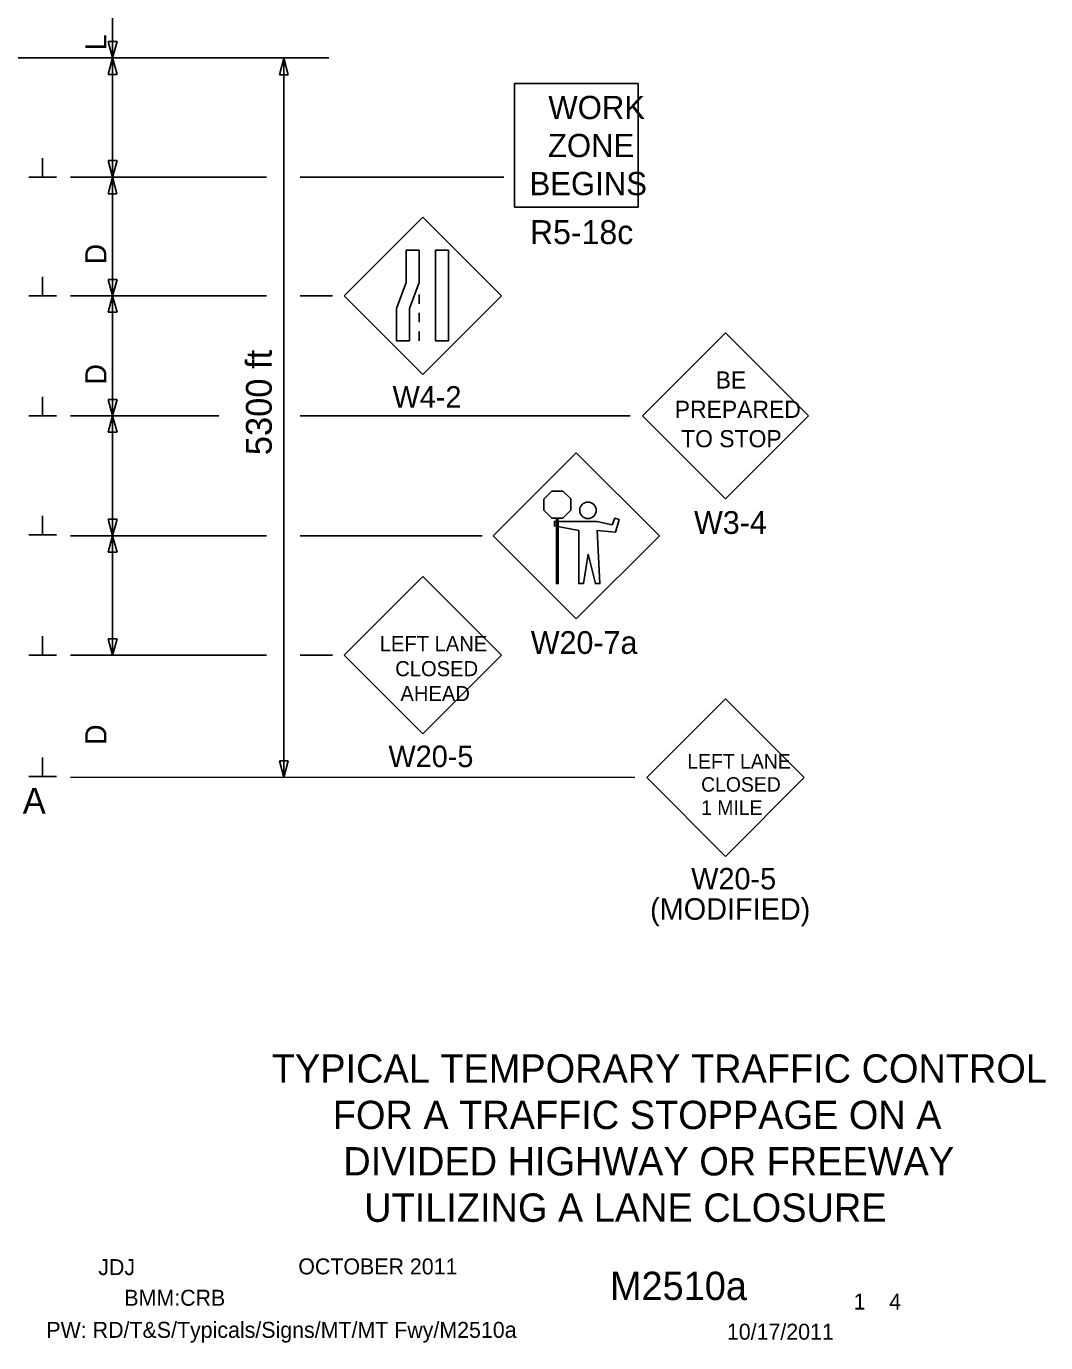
# Model space of a CAD drawing. Extents: x -1809 to 1557, y -1087 to 44.
# Drawn here: x -1388 to -993, y -949 to -438 of the extents above; entities that cross this region are included whole.
import ezdxf

# ---------------------------------------------------------------- set-up
doc = ezdxf.new("R2010")
doc.units = 0
for name, color, linetype in [('BORDER_SIGNAL_WO', 7, 'Continuous'), ('MT_STAGE_1A_NOTES', 7, 'Continuous'), ('TRAFFIC_SIGNS_PR', 7, 'Continuous'), ('TYPICAL_EX', 7, 'Continuous'), ('TYPICAL_TEXT_DIMEN_EX', 7, 'Continuous'), ('TYPICAL_TEXT_DIMEN_PR', 7, 'Continuous')]:
    doc.layers.add(name, color=color, linetype=linetype)

msp = doc.modelspace()

# ---------------------------------------------------------------- linework, layer by layer
at = {"layer": 'MT_STAGE_1A_NOTES'}
for p, q in [((-1354.71, -449.91), (-1354.71, -404)), ((-1270.82, -449.93), (-1476.89, -449.93)), ((-1354.71, -496.05), (-1354.71, -450.14)), ((-1288.23, -449.93), (-1288.23, -729.15)), ((-1295.06, -496.19), (-1371.1, -496.19)), ((-1354.71, -542.28), (-1354.71, -496.37)), ((-1202.88, -496.19), (-1281.88, -496.19)), ((-1295.06, -542.24), (-1371.1, -542.24)), ((-1354.71, -588.34), (-1354.71, -542.43)), ((-1269.38, -542.24), (-1281.88, -542.24)), ((-1313.51, -588.81), (-1371.1, -588.81)), ((-1354.71, -635.22), (-1354.71, -589.31)), ((-1153.88, -588.81), (-1281.88, -588.81)), ((-1295.06, -635.38), (-1371.1, -635.38)), ((-1354.71, -681.41), (-1354.71, -635.5)), ((-1211.38, -635.38), (-1281.88, -635.38)), ((-1295.06, -681.74), (-1371.1, -681.74)), ((-1269.38, -681.74), (-1281.88, -681.74)), ((-1152.1, -729.23), (-1371.1, -729.1))]:
    msp.add_line(p, q, dxfattribs=at)
at = {"layer": 'TRAFFIC_SIGNS_PR'}
for p, q in [((-1198.8, -507.87), (-1198.8, -459.87)), ((-1198.8, -459.87), (-1150.8, -459.87)), ((-1150.8, -507.87), (-1150.8, -459.87)), ((-1198.8, -507.87), (-1150.8, -507.87)), ((-1234.38, -511.69), (-1264.93, -542.24)), ((-1203.84, -542.24), (-1234.38, -511.69)), ((-1264.93, -542.24), (-1234.38, -572.79)), ((-1235.79, -541.69), (-1235.79, -545.29)), ((-1234.38, -572.79), (-1203.84, -542.24)), ((-1235.79, -548.89), (-1235.79, -552.49)), ((-1235.79, -556.09), (-1235.79, -559.69)), ((-1116.91, -556.57), (-1149.16, -588.81)), ((-1084.67, -588.81), (-1116.91, -556.57)), ((-1149.16, -588.81), (-1116.91, -621.05)), ((-1116.91, -621.05), (-1084.67, -588.81)), ((-1174.8, -603.13), (-1207.05, -635.38)), ((-1142.56, -635.38), (-1174.8, -603.13)), ((-1207.05, -635.38), (-1174.8, -667.62)), ((-1174.8, -667.62), (-1142.56, -635.38)), ((-1234.38, -651.19), (-1264.93, -681.74)), ((-1203.84, -681.74), (-1234.38, -651.19)), ((-1264.93, -681.74), (-1234.38, -712.29)), ((-1234.38, -712.29), (-1203.84, -681.74)), ((-1116.91, -698.69), (-1147.46, -729.23)), ((-1086.37, -729.23), (-1116.91, -698.69)), ((-1147.46, -729.23), (-1116.91, -759.78)), ((-1116.91, -759.78), (-1086.37, -729.23))]:
    msp.add_line(p, q, dxfattribs=at)
for points in [[(-1235.79, -524.54), (-1235.79, -537.12), (-1239.55, -547.11), (-1239.55, -559.69), (-1244.6, -559.69), (-1244.6, -547.11), (-1240.84, -537.12), (-1240.84, -524.54)], [(-1224.38, -524.54), (-1224.38, -559.69), (-1229.44, -559.69), (-1229.44, -524.54)], [(-1184.35, -618), (-1179.99, -618), (-1176.9, -621.08), (-1176.9, -625.45), (-1179.99, -628.53), (-1184.35, -628.53), (-1187.43, -625.45), (-1187.43, -621.09)], [(-1166.87, -629.77), (-1183.28, -629.77), (-1183.28, -631.55), (-1173.82, -633.28), (-1173.82, -653.94), (-1172.04, -653.94), (-1170.26, -642.54), (-1167.41, -653.94), (-1165.63, -653.94), (-1166.7, -633.28), (-1159.57, -633.99), (-1158.15, -629.01), (-1159.88, -628.57), (-1160.94, -631.07)], [(-1182.52, -628.53), (-1182.52, -653.92), (-1181.81, -653.92), (-1181.81, -628.53)]]:
    msp.add_lwpolyline(points, close=True, dxfattribs=at)
msp.add_circle((-1170.28, -625.48), 3.21, dxfattribs=at)
at = {"layer": 'TYPICAL_EX'}
for p, q in [((-1381.9, -496.18), (-1381.9, -488.79)), ((-1381.9, -496.18), (-1387.24, -496.18)), ((-1376.55, -496.18), (-1381.9, -496.18)), ((-1381.9, -542.24), (-1381.9, -534.85)), ((-1381.9, -542.24), (-1387.24, -542.24)), ((-1376.55, -542.24), (-1381.9, -542.24)), ((-1381.9, -588.81), (-1381.9, -581.41)), ((-1381.9, -588.81), (-1387.24, -588.81)), ((-1376.55, -588.81), (-1381.9, -588.81)), ((-1381.9, -635.04), (-1381.9, -627.64)), ((-1381.9, -635.04), (-1387.24, -635.04)), ((-1376.55, -635.04), (-1381.9, -635.04)), ((-1381.9, -681.74), (-1381.9, -674.35)), ((-1381.9, -681.74), (-1387.24, -681.74)), ((-1376.55, -681.74), (-1381.9, -681.74)), ((-1381.9, -728.77), (-1381.9, -721.38)), ((-1381.9, -728.77), (-1387.24, -728.77)), ((-1376.55, -728.77), (-1381.9, -728.77))]:
    msp.add_line(p, q, dxfattribs=at)
at = {"layer": 'TYPICAL_TEXT_DIMEN_PR'}
for p, q in [((-1354.7, -443.52), (-1356.4, -443.52)), ((-1356.4, -443.52), (-1354.7, -449.93)), ((-1354.7, -449.93), (-1353.01, -443.52)), ((-1353.01, -443.52), (-1354.7, -443.52)), ((-1354.7, -449.93), (-1356.4, -456.33)), ((-1353.01, -456.33), (-1354.7, -449.93)), ((-1288.23, -450.01), (-1289.93, -456.42)), ((-1286.54, -456.42), (-1288.23, -450.01)), ((-1356.4, -456.33), (-1354.7, -456.33)), ((-1354.7, -456.33), (-1353.01, -456.33)), ((-1289.93, -456.42), (-1288.23, -456.42)), ((-1288.23, -456.42), (-1286.54, -456.42)), ((-1354.71, -489.78), (-1356.4, -489.78)), ((-1356.4, -489.78), (-1354.71, -496.19)), ((-1354.71, -496.19), (-1353.01, -489.78)), ((-1353.01, -489.78), (-1354.71, -489.78)), ((-1354.75, -496.19), (-1356.45, -502.59)), ((-1353.06, -502.59), (-1354.75, -496.19)), ((-1356.45, -502.59), (-1354.75, -502.59)), ((-1354.75, -502.59), (-1353.06, -502.59)), ((-1354.71, -535.84), (-1356.4, -535.84)), ((-1356.4, -535.84), (-1354.71, -542.24)), ((-1354.71, -542.24), (-1353.01, -535.84)), ((-1353.01, -535.84), (-1354.71, -535.84)), ((-1354.71, -542.24), (-1356.4, -548.64)), ((-1353.01, -548.64), (-1354.71, -542.24)), ((-1356.4, -548.64), (-1354.71, -548.64)), ((-1354.71, -548.64), (-1353.01, -548.64)), ((-1354.7, -582.41), (-1356.39, -582.41)), ((-1356.39, -582.41), (-1354.7, -588.81)), ((-1354.7, -588.81), (-1353, -582.41)), ((-1353, -582.41), (-1354.7, -582.41)), ((-1354.7, -588.81), (-1356.39, -595.21)), ((-1353, -595.21), (-1354.7, -588.81)), ((-1356.39, -595.21), (-1354.7, -595.21)), ((-1354.7, -595.21), (-1353, -595.21)), ((-1354.71, -628.97), (-1356.4, -628.97)), ((-1356.4, -628.97), (-1354.71, -635.38)), ((-1354.71, -635.38), (-1353.01, -628.97)), ((-1353.01, -628.97), (-1354.71, -628.97)), ((-1354.71, -635.38), (-1356.4, -641.78)), ((-1353.01, -641.78), (-1354.71, -635.38)), ((-1356.4, -641.78), (-1354.71, -641.78)), ((-1354.71, -641.78), (-1353.01, -641.78)), ((-1354.71, -675.34), (-1356.4, -675.34)), ((-1356.4, -675.34), (-1354.71, -681.74)), ((-1354.71, -681.74), (-1353.01, -675.34)), ((-1353.01, -675.34), (-1354.71, -675.34)), ((-1288.23, -722.75), (-1289.93, -722.75)), ((-1289.93, -722.75), (-1288.23, -729.15)), ((-1288.23, -729.15), (-1286.54, -722.75)), ((-1286.54, -722.75), (-1288.23, -722.75))]:
    msp.add_line(p, q, dxfattribs=at)

# ---------------------------------------------------------------- texts
at = {"layer": 'BORDER_SIGNAL_WO'}
for s, height, p in [('TYPICAL TEMPORARY TRAFFIC CONTROL', 11, (-1292.95, -847.62)), ('FOR A TRAFFIC STOPPAGE ON A', 11, (-1269.28, -865.62)), ('DIVIDED HIGHWAY OR FREEWAY', 11, (-1265.2, -883.62)), ('UTILIZING A LANE CLOSURE', 11, (-1257.11, -901.62)), ('JDJ         ', 6.2, (-1360.28, -922.3)), ('    OCTOBER 2011', 6.2, (-1291.88, -922.02)), ('    M2510a   ', 11, (-1178.1, -931.98)), ('BMM:CRB', 6.2, (-1350.15, -934.19)), (' 1    4 ', 6.2, (-1069.51, -935.66)), ('PW: RD/T&S/Typicals/Signs/MT/MT Fwy/M2510a     ', 6.2, (-1380.41, -946.65)), ('10/17/2011', 6.2, (-1116.37, -947.36))]:
    msp.add_text(s, height=height, dxfattribs=at).set_placement(p)
at = {"layer": 'MT_STAGE_1A_NOTES'}
for s, height, p in [('       L', 8.25, (-1357.1, -468.42)), ('                     D', 8.25, (-1357.1, -594.41)), ('5300 ft', 10, (-1292.97, -604.09)), ('                     D', 8.25, (-1357.1, -641.04)), ('                     D', 8.25, (-1357.1, -780.92))]:
    msp.add_text(s, height=height, rotation=90, dxfattribs=at).set_placement(p)
at = {"layer": 'TRAFFIC_SIGNS_PR'}
for s, height, p in [('WORK', 9.021, (-1185.65, -473.66)), ('ZONE', 9.021, (-1185.8, -488.42)), ('BEGINS', 9.021, (-1192.96, -503.18)), ('R5-18c', 9.3, (-1192.79, -522.17)), ('BE', 6.65, (-1120.73, -578.21)), ('W4-2', 8.37, (-1246.09, -585.66)), ('PREPARED', 6.65, (-1136.61, -589.61)), ('TO STOP', 6.65, (-1134.14, -601.01)), ('W3-4', 8.835, (-1129.11, -634.64)), ('LEFT LANE', 5.85, (-1251.08, -680.17)), ('W20-7a', 8.835, (-1192.45, -681.21)), ('CLOSED', 5.85, (-1245.06, -689.85)), ('AHEAD', 5.85, (-1243.05, -699.52)), ('W20-5', 8.37, (-1247.69, -725.16)), ('LEFT LANE', 5.624, (-1131.73, -725.69)), ('CLOSED', 5.624, (-1126.38, -734.68)), ('1 MILE', 5.624, (-1126.38, -743.68)), ('W20-5', 8.369, (-1130.22, -772.64)), ('(MODIFIED)', 8.369, (-1146.17, -784.39))]:
    msp.add_text(s, height=height, dxfattribs=at).set_placement(p)
at = {"layer": 'TYPICAL_TEXT_DIMEN_EX'}
msp.add_text('A MATCH LINE A', height=10, dxfattribs=at).set_placement((-1486.91, -743.19))

doc.saveas('drawing.dxf')
